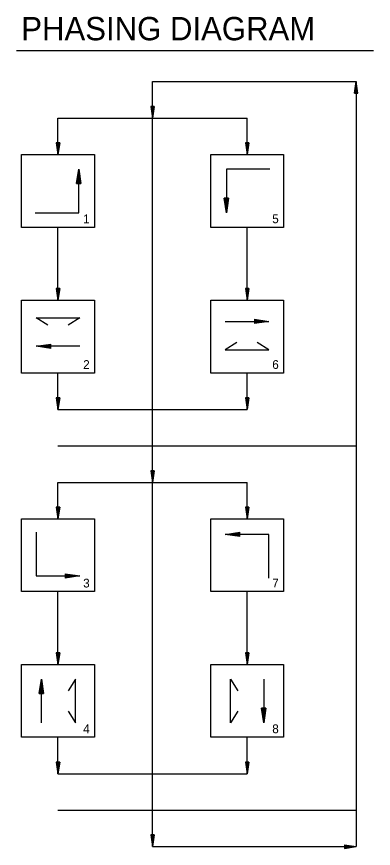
# Model space of a CAD drawing. Extents: x -15.7 to 19.3, y -1.4 to 10.8.
# Drawn here: x 3.895 to 5.939, y 6.021 to 10.778 of the extents above; entities that cross this region are included whole.
import ezdxf

# ---------------------------------------------------------------- set-up
doc = ezdxf.new("R2010")
doc.units = 0
for name, color, linetype in [('R_Draft', 7, 'Continuous'), ('T_Drafting', 7, 'Continuous'), ('T_Notes', 7, 'Continuous')]:
    doc.layers.add(name, color=color, linetype=linetype)

msp = doc.modelspace()

# ---------------------------------------------------------------- linework, layer by layer
at = {"layer": 'R_Draft'}
for p, q in [((5.8306, 10.3397), (5.8406, 10.4064)), ((5.8322, 10.3397), (5.8406, 10.3953)), ((5.8339, 10.3397), (5.8406, 10.3838)), ((5.8356, 10.3397), (5.8406, 10.3727)), ((5.8506, 10.3397), (5.8406, 10.4064)), ((5.8489, 10.3397), (5.8406, 10.3953)), ((5.8472, 10.3397), (5.8406, 10.3838)), ((5.8455, 10.3397), (5.8406, 10.3727)), ((5.8306, 10.3397), (5.8506, 10.3397)), ((5.8373, 10.3397), (5.8406, 10.3614)), ((5.839, 10.3397), (5.8406, 10.3503)), ((5.8438, 10.3397), (5.8406, 10.3614)), ((5.8421, 10.3397), (5.8406, 10.3503)), ((4.6639, 10.2647), (4.6739, 10.1981)), ((4.6839, 10.2647), (4.6639, 10.2647)), ((4.6656, 10.2647), (4.6739, 10.2092)), ((4.6673, 10.2647), (4.6739, 10.2207)), ((4.6689, 10.2647), (4.6739, 10.2318)), ((4.6706, 10.2647), (4.6739, 10.2431)), ((4.6723, 10.2647), (4.6739, 10.2542)), ((4.6839, 10.2647), (4.6739, 10.1981)), ((4.6771, 10.2647), (4.6739, 10.2431)), ((4.6805, 10.2647), (4.6739, 10.2207)), ((4.6822, 10.2647), (4.6739, 10.2092)), ((4.6789, 10.2647), (4.6739, 10.2318)), ((4.6755, 10.2647), (4.6739, 10.2542)), ((4.1222, 10.0564), (4.1322, 9.9897)), ((4.1422, 10.0564), (4.1222, 10.0564)), ((4.1239, 10.0564), (4.1322, 10.0009)), ((4.1256, 10.0564), (4.1322, 10.0123)), ((4.1273, 10.0564), (4.1322, 10.0234)), ((4.129, 10.0564), (4.1322, 10.0347)), ((4.1307, 10.0564), (4.1322, 10.0459)), ((4.1422, 10.0564), (4.1322, 9.9897)), ((4.1355, 10.0564), (4.1322, 10.0347)), ((4.1389, 10.0564), (4.1322, 10.0123)), ((4.1406, 10.0564), (4.1322, 10.0009)), ((4.1372, 10.0564), (4.1322, 10.0234)), ((4.1338, 10.0564), (4.1322, 10.0459)), ((5.2056, 10.0564), (5.2156, 9.9897)), ((5.2256, 10.0564), (5.2056, 10.0564)), ((5.2072, 10.0564), (5.2156, 10.0009)), ((5.2089, 10.0564), (5.2156, 10.0123)), ((5.2106, 10.0564), (5.2156, 10.0234)), ((5.2123, 10.0564), (5.2156, 10.0347)), ((5.214, 10.0564), (5.2156, 10.0459)), ((5.2256, 10.0564), (5.2156, 9.9897)), ((5.2188, 10.0564), (5.2156, 10.0347)), ((5.2222, 10.0564), (5.2156, 10.0123)), ((5.2239, 10.0564), (5.2156, 10.0009)), ((5.2205, 10.0564), (5.2156, 10.0234)), ((5.2171, 10.0564), (5.2156, 10.0459)), ((4.1222, 9.2231), (4.1322, 9.1564)), ((4.1422, 9.2231), (4.1222, 9.2231)), ((4.1239, 9.2231), (4.1322, 9.1675)), ((4.1256, 9.2231), (4.1322, 9.179)), ((4.1273, 9.2231), (4.1322, 9.1901)), ((4.129, 9.2231), (4.1322, 9.2014)), ((4.1307, 9.2231), (4.1322, 9.2125)), ((4.1422, 9.2231), (4.1322, 9.1564)), ((4.1355, 9.2231), (4.1322, 9.2014)), ((4.1389, 9.2231), (4.1322, 9.179)), ((4.1406, 9.2231), (4.1322, 9.1675)), ((4.1372, 9.2231), (4.1322, 9.1901)), ((4.1338, 9.2231), (4.1322, 9.2125)), ((5.2056, 9.2231), (5.2156, 9.1564)), ((5.2256, 9.2231), (5.2056, 9.2231)), ((5.2072, 9.2231), (5.2156, 9.1675)), ((5.2089, 9.2231), (5.2156, 9.179)), ((5.2106, 9.2231), (5.2156, 9.1901)), ((5.2123, 9.2231), (5.2156, 9.2014)), ((5.214, 9.2231), (5.2156, 9.2125)), ((5.2256, 9.2231), (5.2156, 9.1564)), ((5.2188, 9.2231), (5.2156, 9.2014)), ((5.2222, 9.2231), (5.2156, 9.179)), ((5.2239, 9.2231), (5.2156, 9.1675)), ((5.2205, 9.2231), (5.2156, 9.1901)), ((5.2171, 9.2231), (5.2156, 9.2125)), ((4.1222, 8.5981), (4.1322, 8.5314)), ((4.1422, 8.5981), (4.1222, 8.5981)), ((4.1239, 8.5981), (4.1322, 8.5425)), ((4.1256, 8.5981), (4.1322, 8.554)), ((4.1273, 8.5981), (4.1322, 8.5651)), ((4.129, 8.5981), (4.1322, 8.5764)), ((4.1307, 8.5981), (4.1322, 8.5875)), ((4.1422, 8.5981), (4.1322, 8.5314)), ((4.1355, 8.5981), (4.1322, 8.5764)), ((4.1389, 8.5981), (4.1322, 8.554)), ((4.1406, 8.5981), (4.1322, 8.5425)), ((4.1372, 8.5981), (4.1322, 8.5651)), ((4.1338, 8.5981), (4.1322, 8.5875)), ((5.2056, 8.5981), (5.2156, 8.5314)), ((5.2256, 8.5981), (5.2056, 8.5981)), ((5.2072, 8.5981), (5.2156, 8.5425)), ((5.2089, 8.5981), (5.2156, 8.554)), ((5.2106, 8.5981), (5.2156, 8.5651)), ((5.2123, 8.5981), (5.2156, 8.5764)), ((5.214, 8.5981), (5.2156, 8.5875)), ((5.2256, 8.5981), (5.2156, 8.5314)), ((5.2188, 8.5981), (5.2156, 8.5764)), ((5.2222, 8.5981), (5.2156, 8.554)), ((5.2239, 8.5981), (5.2156, 8.5425)), ((5.2205, 8.5981), (5.2156, 8.5651)), ((5.2171, 8.5981), (5.2156, 8.5875)), ((4.6639, 8.1814), (4.6739, 8.1147)), ((4.6839, 8.1814), (4.6639, 8.1814)), ((4.6656, 8.1814), (4.6739, 8.1259)), ((4.6673, 8.1814), (4.6739, 8.1373)), ((4.6689, 8.1814), (4.6739, 8.1484)), ((4.6706, 8.1814), (4.6739, 8.1597)), ((4.6723, 8.1814), (4.6739, 8.1709)), ((4.6839, 8.1814), (4.6739, 8.1147)), ((4.6771, 8.1814), (4.6739, 8.1597)), ((4.6805, 8.1814), (4.6739, 8.1373)), ((4.6822, 8.1814), (4.6739, 8.1259)), ((4.6789, 8.1814), (4.6739, 8.1484)), ((4.6755, 8.1814), (4.6739, 8.1709)), ((4.1222, 7.9731), (4.1322, 7.9064)), ((4.1422, 7.9731), (4.1222, 7.9731)), ((4.1239, 7.9731), (4.1322, 7.9175)), ((4.1256, 7.9731), (4.1322, 7.929)), ((4.1273, 7.9731), (4.1322, 7.9401)), ((4.129, 7.9731), (4.1322, 7.9514)), ((4.1307, 7.9731), (4.1322, 7.9625)), ((4.1422, 7.9731), (4.1322, 7.9064)), ((4.1355, 7.9731), (4.1322, 7.9514)), ((4.1389, 7.9731), (4.1322, 7.929)), ((4.1406, 7.9731), (4.1322, 7.9175)), ((4.1372, 7.9731), (4.1322, 7.9401)), ((4.1338, 7.9731), (4.1322, 7.9625)), ((5.2056, 7.9731), (5.2156, 7.9064)), ((5.2256, 7.9731), (5.2056, 7.9731)), ((5.2072, 7.9731), (5.2156, 7.9175)), ((5.2089, 7.9731), (5.2156, 7.929)), ((5.2106, 7.9731), (5.2156, 7.9401)), ((5.2123, 7.9731), (5.2156, 7.9514)), ((5.214, 7.9731), (5.2156, 7.9625)), ((5.2256, 7.9731), (5.2156, 7.9064)), ((5.2188, 7.9731), (5.2156, 7.9514)), ((5.2222, 7.9731), (5.2156, 7.929)), ((5.2239, 7.9731), (5.2156, 7.9175)), ((5.2205, 7.9731), (5.2156, 7.9401)), ((5.2171, 7.9731), (5.2156, 7.9625)), ((4.1222, 7.1397), (4.1322, 7.0731)), ((4.1422, 7.1397), (4.1222, 7.1397)), ((4.1239, 7.1397), (4.1322, 7.0842)), ((4.1256, 7.1397), (4.1322, 7.0957)), ((4.1273, 7.1397), (4.1322, 7.1068)), ((4.129, 7.1397), (4.1322, 7.1181)), ((4.1307, 7.1397), (4.1322, 7.1292)), ((4.1422, 7.1397), (4.1322, 7.0731)), ((4.1355, 7.1397), (4.1322, 7.1181)), ((4.1389, 7.1397), (4.1322, 7.0957)), ((4.1406, 7.1397), (4.1322, 7.0842)), ((4.1372, 7.1397), (4.1322, 7.1068)), ((4.1338, 7.1397), (4.1322, 7.1292)), ((5.2056, 7.1397), (5.2156, 7.0731)), ((5.2256, 7.1397), (5.2056, 7.1397)), ((5.2072, 7.1397), (5.2156, 7.0842)), ((5.2089, 7.1397), (5.2156, 7.0957)), ((5.2106, 7.1397), (5.2156, 7.1068)), ((5.2123, 7.1397), (5.2156, 7.1181)), ((5.214, 7.1397), (5.2156, 7.1292)), ((5.2256, 7.1397), (5.2156, 7.0731)), ((5.2188, 7.1397), (5.2156, 7.1181)), ((5.2222, 7.1397), (5.2156, 7.0957)), ((5.2239, 7.1397), (5.2156, 7.0842)), ((5.2205, 7.1397), (5.2156, 7.1068)), ((5.2171, 7.1397), (5.2156, 7.1292)), ((4.1222, 6.5147), (4.1322, 6.4481)), ((4.1422, 6.5147), (4.1222, 6.5147)), ((4.1239, 6.5147), (4.1322, 6.4592)), ((4.1256, 6.5147), (4.1322, 6.4707)), ((4.1273, 6.5147), (4.1322, 6.4818)), ((4.129, 6.5147), (4.1322, 6.4931)), ((4.1307, 6.5147), (4.1322, 6.5042)), ((4.1422, 6.5147), (4.1322, 6.4481)), ((4.1355, 6.5147), (4.1322, 6.4931)), ((4.1389, 6.5147), (4.1322, 6.4707)), ((4.1406, 6.5147), (4.1322, 6.4592)), ((4.1372, 6.5147), (4.1322, 6.4818)), ((4.1338, 6.5147), (4.1322, 6.5042)), ((5.2056, 6.5147), (5.2156, 6.4481)), ((5.2256, 6.5147), (5.2056, 6.5147)), ((5.2072, 6.5147), (5.2156, 6.4592)), ((5.2089, 6.5147), (5.2156, 6.4707)), ((5.2106, 6.5147), (5.2156, 6.4818)), ((5.2123, 6.5147), (5.2156, 6.4931)), ((5.214, 6.5147), (5.2156, 6.5042)), ((5.2256, 6.5147), (5.2156, 6.4481)), ((5.2188, 6.5147), (5.2156, 6.4931)), ((5.2222, 6.5147), (5.2156, 6.4707)), ((5.2239, 6.5147), (5.2156, 6.4592)), ((5.2205, 6.5147), (5.2156, 6.4818)), ((5.2171, 6.5147), (5.2156, 6.5042)), ((4.6639, 6.0981), (4.6739, 6.0314)), ((4.6839, 6.0981), (4.6639, 6.0981)), ((4.6656, 6.0981), (4.6739, 6.0425)), ((4.6673, 6.0981), (4.6739, 6.054)), ((4.6689, 6.0981), (4.6739, 6.0651)), ((4.6706, 6.0981), (4.6739, 6.0764)), ((4.6723, 6.0981), (4.6739, 6.0875)), ((4.6839, 6.0981), (4.6739, 6.0314)), ((4.6771, 6.0981), (4.6739, 6.0764)), ((4.6805, 6.0981), (4.6739, 6.054)), ((4.6822, 6.0981), (4.6739, 6.0425)), ((4.6789, 6.0981), (4.6739, 6.0651)), ((4.6755, 6.0981), (4.6739, 6.0875)), ((5.7739, 6.0414), (5.8406, 6.0314)), ((5.7739, 6.0414), (5.7739, 6.0214)), ((5.7739, 6.0397), (5.8294, 6.0314)), ((5.7739, 6.038), (5.818, 6.0314)), ((5.7739, 6.0364), (5.8069, 6.0314)), ((5.7739, 6.0346), (5.7956, 6.0314)), ((5.7739, 6.033), (5.7844, 6.0314)), ((5.7739, 6.0214), (5.8406, 6.0314)), ((5.7739, 6.0281), (5.7956, 6.0314)), ((5.7739, 6.0248), (5.818, 6.0314)), ((5.7739, 6.0231), (5.8294, 6.0314)), ((5.7739, 6.0264), (5.8069, 6.0314)), ((5.7739, 6.0298), (5.7844, 6.0314))]:
    msp.add_line(p, q, dxfattribs=at)
at = {"layer": 'T_Drafting'}
for p, q in [((4.6739, 6.0314), (4.6739, 10.4064)), ((4.6739, 10.4064), (5.8406, 10.4064)), ((5.8406, 10.4064), (5.8406, 6.0314)), ((4.1322, 9.9897), (4.1322, 10.1981)), ((4.1322, 10.1981), (5.2156, 10.1981)), ((5.2156, 9.9897), (5.2156, 10.1981)), ((4.2385, 9.8231), (4.251, 9.9064)), ((4.251, 9.6564), (4.251, 9.9064)), ((4.251, 9.9064), (4.2635, 9.8231)), ((5.3468, 9.9064), (5.0968, 9.9064)), ((5.0968, 9.9064), (5.0968, 9.6564)), ((4.251, 9.8925), (4.2406, 9.8231)), ((4.2427, 9.8231), (4.251, 9.8781)), ((4.251, 9.8643), (4.2448, 9.8231)), ((4.2469, 9.8231), (4.251, 9.8501)), ((4.2614, 9.8231), (4.251, 9.8925)), ((4.251, 9.8781), (4.2593, 9.8231)), ((4.2572, 9.8231), (4.251, 9.8643)), ((4.251, 9.8501), (4.2551, 9.8231)), ((4.2385, 9.8231), (4.2635, 9.8231)), ((4.251, 9.8362), (4.249, 9.8231)), ((4.2529, 9.8231), (4.251, 9.8362)), ((5.0968, 9.6564), (5.0843, 9.7397)), ((5.1093, 9.7397), (5.0843, 9.7397)), ((5.0864, 9.7397), (5.0968, 9.6703)), ((5.0968, 9.6846), (5.0885, 9.7397)), ((5.0906, 9.7397), (5.0968, 9.6985)), ((5.0968, 9.7126), (5.0927, 9.7397)), ((5.0948, 9.7397), (5.0968, 9.7266)), ((5.0968, 9.7266), (5.0988, 9.7397)), ((5.1008, 9.7397), (5.0968, 9.7126)), ((5.0968, 9.6985), (5.103, 9.7397)), ((5.1051, 9.7397), (5.0968, 9.6846)), ((5.0968, 9.6703), (5.1072, 9.7397)), ((5.1093, 9.7397), (5.0968, 9.6564)), ((4.001, 9.6564), (4.251, 9.6564)), ((4.1322, 9.1564), (4.1322, 9.5731)), ((5.2156, 9.1564), (5.2156, 9.5731)), ((5.2572, 9.0478), (5.3406, 9.0353)), ((5.2572, 9.0478), (5.2572, 9.0228)), ((5.3266, 9.0353), (5.2572, 9.0457)), ((5.2572, 9.0436), (5.3123, 9.0353)), ((5.2984, 9.0353), (5.2572, 9.0415)), ((5.2572, 9.0394), (5.2843, 9.0353)), ((5.0906, 9.0353), (5.3406, 9.0353)), ((5.2704, 9.0353), (5.2572, 9.0373)), ((5.3406, 9.0353), (5.2572, 9.0228)), ((5.2572, 9.0249), (5.3266, 9.0353)), ((5.3123, 9.0353), (5.2572, 9.027)), ((5.2572, 9.0291), (5.2984, 9.0353)), ((5.2843, 9.0353), (5.2572, 9.0312)), ((5.2572, 9.0334), (5.2704, 9.0353)), ((4.0072, 8.8928), (4.0906, 8.9053)), ((4.0906, 8.9032), (4.0211, 8.8928)), ((4.0355, 8.8928), (4.0906, 8.9011)), ((4.0906, 8.899), (4.0493, 8.8928)), ((4.0635, 8.8928), (4.0906, 8.8969)), ((4.0906, 8.8803), (4.0906, 8.9053)), ((4.2572, 8.8928), (4.0072, 8.8928)), ((4.0906, 8.8803), (4.0072, 8.8928)), ((4.0211, 8.8928), (4.0906, 8.8824)), ((4.0906, 8.8845), (4.0355, 8.8928)), ((4.0493, 8.8928), (4.0906, 8.8866)), ((4.0906, 8.8887), (4.0635, 8.8928)), ((4.0906, 8.8947), (4.0774, 8.8928)), ((4.0774, 8.8928), (4.0906, 8.8908)), ((4.1322, 8.5314), (4.1322, 8.7397)), ((5.2156, 8.5314), (5.2156, 8.7397)), ((4.1322, 8.5314), (5.2156, 8.5314)), ((4.1322, 8.3231), (5.8406, 8.3231)), ((4.1322, 8.1147), (5.2156, 8.1147)), ((4.1322, 7.9064), (4.1322, 8.1147)), ((5.2156, 7.9064), (5.2156, 8.1147)), ((4.0072, 7.8293), (4.0072, 7.5793)), ((5.0906, 7.8168), (5.1739, 7.8293)), ((5.3406, 7.8168), (5.0906, 7.8168)), ((5.1739, 7.8043), (5.0906, 7.8168)), ((5.1739, 7.8272), (5.1045, 7.8168)), ((5.1045, 7.8168), (5.1739, 7.8064)), ((5.1188, 7.8168), (5.1739, 7.8251)), ((5.1739, 7.8085), (5.1188, 7.8168)), ((5.1739, 7.823), (5.1327, 7.8168)), ((5.1327, 7.8168), (5.1739, 7.8106)), ((5.1468, 7.8168), (5.1739, 7.8209)), ((5.1739, 7.8128), (5.1468, 7.8168)), ((5.1739, 7.8188), (5.1607, 7.8168)), ((5.1607, 7.8168), (5.1739, 7.8148)), ((5.1739, 7.8043), (5.1739, 7.8293)), ((5.3406, 7.5668), (5.3406, 7.8168)), ((4.0072, 7.5793), (4.2572, 7.5793)), ((4.1739, 7.5918), (4.2572, 7.5793)), ((4.1739, 7.5918), (4.1739, 7.5668)), ((4.2433, 7.5793), (4.1739, 7.5897)), ((4.1739, 7.5876), (4.229, 7.5793)), ((4.2151, 7.5793), (4.1739, 7.5855)), ((4.1739, 7.5833), (4.201, 7.5793)), ((4.1871, 7.5793), (4.1739, 7.5813)), ((4.2572, 7.5793), (4.1739, 7.5668)), ((4.1739, 7.5689), (4.2433, 7.5793)), ((4.229, 7.5793), (4.1739, 7.571)), ((4.1739, 7.5731), (4.2151, 7.5793)), ((4.201, 7.5793), (4.1739, 7.5752)), ((4.1739, 7.5773), (4.1871, 7.5793)), ((4.1322, 7.0731), (4.1322, 7.4897)), ((5.2156, 7.0731), (5.2156, 7.4897)), ((4.0244, 6.9064), (4.0369, 6.9897)), ((4.0369, 6.9758), (4.0265, 6.9064)), ((4.0286, 6.9064), (4.0369, 6.9615)), ((4.0369, 6.9476), (4.0307, 6.9064)), ((4.0369, 6.7397), (4.0369, 6.9897)), ((4.0369, 6.9897), (4.0494, 6.9064)), ((4.0473, 6.9064), (4.0369, 6.9758)), ((4.0369, 6.9615), (4.0452, 6.9064)), ((4.0431, 6.9064), (4.0369, 6.9476)), ((5.3109, 6.9897), (5.3109, 6.7397)), ((4.0244, 6.9064), (4.0494, 6.9064)), ((4.0329, 6.9064), (4.0369, 6.9335)), ((4.0369, 6.9196), (4.0349, 6.9064)), ((4.0369, 6.9335), (4.041, 6.9064)), ((4.0389, 6.9064), (4.0369, 6.9196)), ((5.3109, 6.7397), (5.2984, 6.8231)), ((5.3234, 6.8231), (5.2984, 6.8231)), ((5.3005, 6.8231), (5.3109, 6.7536)), ((5.3109, 6.768), (5.3026, 6.8231)), ((5.3047, 6.8231), (5.3109, 6.7818)), ((5.3109, 6.796), (5.3068, 6.8231)), ((5.3089, 6.8231), (5.3109, 6.8099)), ((5.3109, 6.8099), (5.3128, 6.8231)), ((5.3149, 6.8231), (5.3109, 6.796)), ((5.3109, 6.7818), (5.3171, 6.8231)), ((5.3192, 6.8231), (5.3109, 6.768)), ((5.3109, 6.7536), (5.3213, 6.8231)), ((5.3234, 6.8231), (5.3109, 6.7397)), ((4.1322, 6.4481), (4.1322, 6.6564)), ((5.2156, 6.4481), (5.2156, 6.6564)), ((4.1322, 6.4481), (5.2156, 6.4481)), ((4.1322, 6.2397), (5.8406, 6.2397)), ((4.6739, 6.0314), (5.8406, 6.0314))]:
    msp.add_line(p, q, dxfattribs=at)
for points in [[(3.9239, 9.9897), (4.3406, 9.9897), (4.3406, 9.5731), (3.9239, 9.5731)], [(5.0072, 9.9897), (5.4239, 9.9897), (5.4239, 9.5731), (5.0072, 9.5731)], [(3.9239, 9.1564), (4.3406, 9.1564), (4.3406, 8.7397), (3.9239, 8.7397)], [(5.0072, 9.1564), (5.4239, 9.1564), (5.4239, 8.7397), (5.0072, 8.7397)], [(3.9239, 7.9064), (4.3406, 7.9064), (4.3406, 7.4897), (3.9239, 7.4897)], [(5.0072, 7.9064), (5.4239, 7.9064), (5.4239, 7.4897), (5.0072, 7.4897)], [(3.9239, 7.0731), (4.3406, 7.0731), (4.3406, 6.6564), (3.9239, 6.6564)], [(5.0072, 7.0731), (5.4239, 7.0731), (5.4239, 6.6564), (5.0072, 6.6564)]]:
    msp.add_lwpolyline(points, close=True, dxfattribs=at)
for points in [[(4.0739, 9.0145), (4.0072, 9.0562), (4.2572, 9.0562), (4.1906, 9.0145)], [(5.1572, 8.9136), (5.0906, 8.8719), (5.3406, 8.8719), (5.2739, 8.9136)], [(4.1908, 6.8064), (4.2325, 6.7397), (4.2325, 6.9897), (4.1908, 6.9231)], [(5.1619, 6.8064), (5.1202, 6.7397), (5.1202, 6.9897), (5.1619, 6.9231)]]:
    msp.add_lwpolyline(points, dxfattribs=at)
at = {"layer": 'T_Notes'}
msp.add_line((3.8951, 10.585), (5.9392, 10.585), dxfattribs=at)

# ---------------------------------------------------------------- texts
for s, height, p in [('PHASING DIAGRAM', 0.133333, (3.9217, 10.6428)), ('1', 0.05, (4.2765, 9.5968)), ('5', 0.05, (5.3598, 9.5968)), ('2', 0.05, (4.2765, 8.7634)), ('6', 0.05, (5.3598, 8.7634)), ('3', 0.05, (4.2765, 7.5134)), ('7', 0.05, (5.3598, 7.5134)), ('4', 0.05, (4.2765, 6.6801)), ('8', 0.05, (5.3598, 6.6801))]:
    msp.add_text(s, height=height, dxfattribs=at).set_placement(p)

doc.saveas('drawing.dxf')
